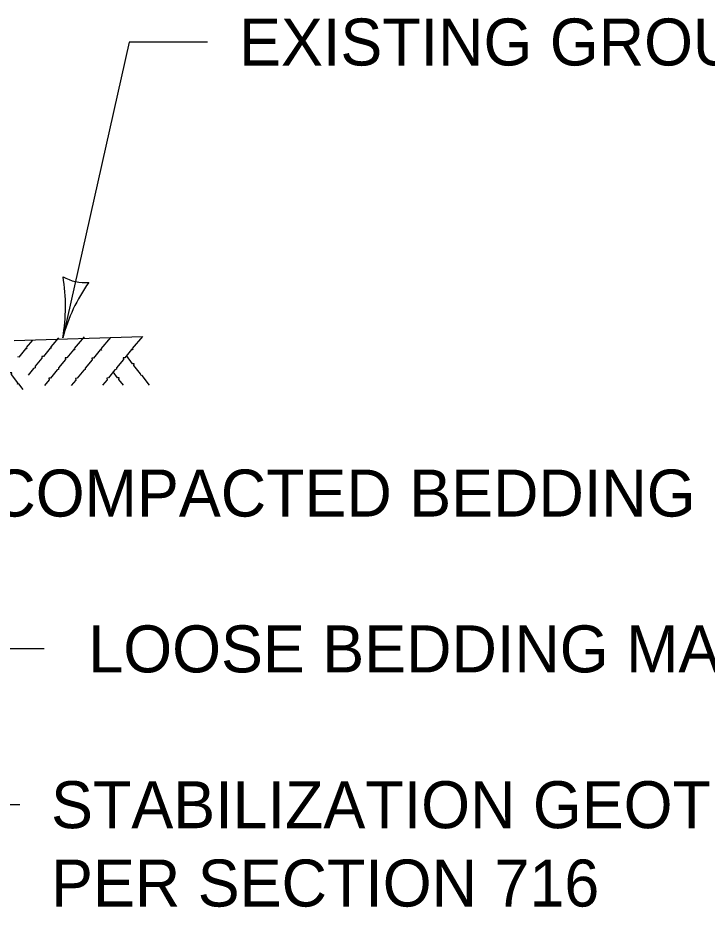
# Model space of a CAD drawing. Extents: x 49991.4 to 50021, y 49987.6 to 50011.4.
# Drawn here: x 50005.577 to 50006.457, y 49989.151 to 49990.286 of the extents above; entities that cross this region are included whole.
import ezdxf

# ---------------------------------------------------------------- set-up
doc = ezdxf.new("R2010")
doc.units = 0
for name, color, linetype in [('Level 1', 7, 'Continuous'), ('Level 2', 7, 'Continuous'), ('Level 3', 7, 'Continuous')]:
    doc.layers.add(name, color=color, linetype=linetype)

msp = doc.modelspace()

# ---------------------------------------------------------------- linework, layer by layer
at = {"layer": 'Level 1'}
msp.add_line((50005.5724, 49989.8745), (50005.7362, 49989.8794), dxfattribs=at)
for points in [[(50005.5959, 49989.875), (50005.5877, 49989.8654), (50005.5885, 49989.8638), (50005.5869, 49989.8638), (50005.5784, 49989.8533), (50005.5773, 49989.8534)], [(50005.6291, 49989.8777), (50005.6191, 49989.8661), (50005.6199, 49989.8645), (50005.6183, 49989.8645), (50005.6098, 49989.854), (50005.6077, 49989.8541), (50005.6079, 49989.852), (50005.5991, 49989.8415), (50005.5991, 49989.8394), (50005.5972, 49989.8388), (50005.5903, 49989.8301)], [(50005.6619, 49989.8789), (50005.6492, 49989.8641), (50005.65, 49989.8625), (50005.6484, 49989.8625), (50005.6399, 49989.8521), (50005.6377, 49989.8521), (50005.638, 49989.8501), (50005.6292, 49989.8395), (50005.6292, 49989.8374), (50005.6273, 49989.8368), (50005.6189, 49989.8263), (50005.6169, 49989.8262), (50005.6173, 49989.8242), (50005.6112, 49989.8171)], [(50005.6956, 49989.8783), (50005.6833, 49989.8638), (50005.684, 49989.8622), (50005.6824, 49989.8623), (50005.6739, 49989.8518), (50005.6718, 49989.8518), (50005.672, 49989.8498), (50005.6632, 49989.8392), (50005.6632, 49989.8372), (50005.6613, 49989.8365), (50005.653, 49989.8261), (50005.651, 49989.8259), (50005.6513, 49989.8239), (50005.6453, 49989.8168)], [(50005.7362, 49989.8794), (50005.7232, 49989.8643), (50005.7239, 49989.8626), (50005.7223, 49989.8627), (50005.7138, 49989.8522), (50005.7117, 49989.8522), (50005.7119, 49989.8502), (50005.7032, 49989.8396), (50005.7031, 49989.8376), (50005.7012, 49989.8369), (50005.6929, 49989.8265), (50005.6908, 49989.8264), (50005.6912, 49989.8243), (50005.6852, 49989.8172)], [(50005.5838, 49989.8119), (50005.5785, 49989.8192), (50005.5768, 49989.8188), (50005.5772, 49989.8203), (50005.5689, 49989.831), (50005.5694, 49989.833), (50005.5674, 49989.8333), (50005.559, 49989.8442), (50005.5571, 49989.8447), (50005.5569, 49989.8467), (50005.5486, 49989.8572), (50005.5489, 49989.8592), (50005.5469, 49989.8593), (50005.5374, 49989.8719)], [(50005.7455, 49989.8172), (50005.736, 49989.8296), (50005.7341, 49989.8301), (50005.7339, 49989.832), (50005.7255, 49989.8426), (50005.7259, 49989.8445), (50005.7238, 49989.8446), (50005.716, 49989.8551)], [(50005.7122, 49989.8172), (50005.7063, 49989.8247), (50005.7067, 49989.8267), (50005.7046, 49989.8268), (50005.6989, 49989.8344)]]:
    msp.add_lwpolyline(points, dxfattribs=at)
at = {"layer": 'Level 3'}
for p, q in [((50005.7194, 49990.2554), (50005.6346, 49989.8779)), ((50005.8194, 49990.2554), (50005.7194, 49990.2554)), ((50005.611, 49989.4807), (50004.4589, 49989.4807)), ((50005.5796, 49989.2818), (50004.4589, 49989.2818))]:
    msp.add_line(p, q, dxfattribs=at)
for centre, radius, start, end in [((50005.405, 49989.9177), 0.233, 350.1728, 9.4227), ((50005.6627, 49990.003), 0.0548, 239.4843, 275.2067), ((50005.8493, 49989.8203), 0.2223, 144.8015, 164.985)]:
    msp.add_arc(centre, radius, start, end, dxfattribs=at)

# ---------------------------------------------------------------- texts
at = {"layer": 'Level 2'}
for s, p in [('EXISTING GROUND', (50005.8597, 49990.2254)), ('COMPACTED BEDDING MATERIAL', (50005.5421, 49989.6496)), ('LOOSE BEDDING MATERIAL', (50005.6672, 49989.4507)), ('STABILIZATION GEOTEXTILE', (50005.6196, 49989.2518)), ('PER SECTION 716', (50005.6196, 49989.1518))]:
    msp.add_text(s, height=0.06, dxfattribs=at).set_placement(p)

doc.saveas('drawing.dxf')
